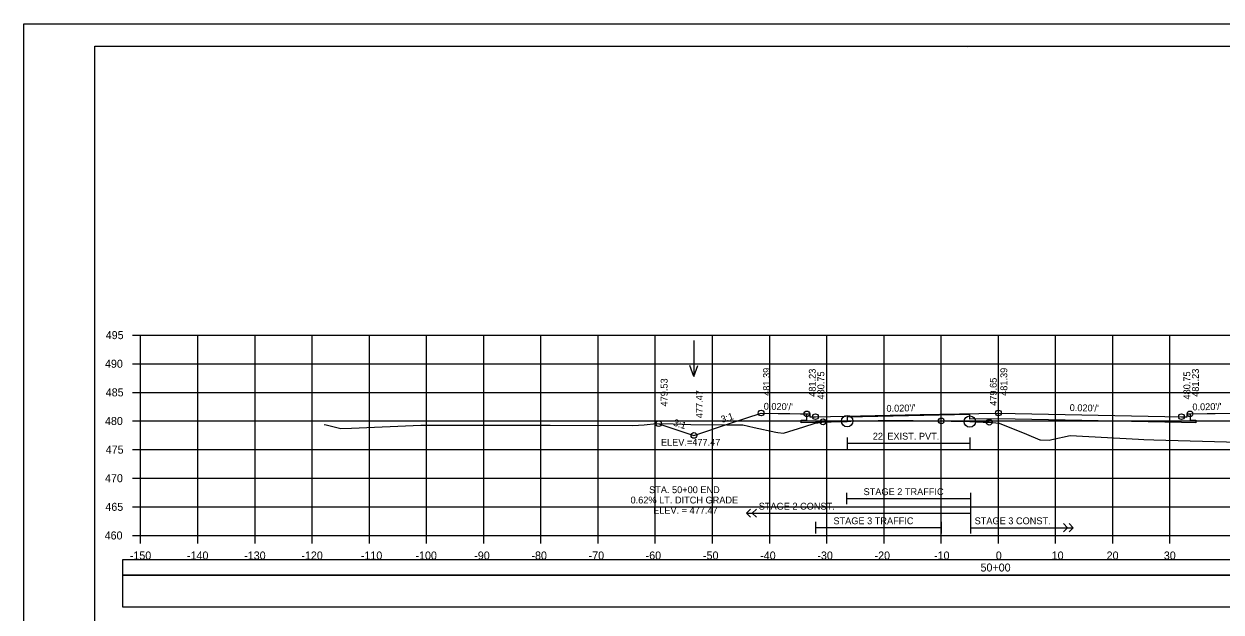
# Model space of a CAD drawing. Extents: x 1371057 to 1372761, y 380005 to 390517.
# Drawn here: x 1371390.5 to 1371599.8, y 383102.4 to 383205.1 of the extents above; entities that cross this region are included whole.
import ezdxf

# ---------------------------------------------------------------- set-up
doc = ezdxf.new("R2010")
doc.units = 0
for name, color, linetype in [('R_Alt Surface', 7, 'Continuous'), ('R_Axis', 7, 'Continuous'), ('R_Axis Annot', 7, 'Continuous'), ('R_Border', 7, 'Continuous'), ('R_Detour', 7, 'Continuous'), ('R_Dimension', 7, 'Continuous'), ('R_Exist Surface', 7, 'Continuous'), ('R_Fin Surface', 7, 'Continuous'), ('R_Grid', 7, 'Continuous'), ('R_No Plot', 7, 'Continuous'), ('R_Striping', 7, 'Continuous'), ('R_Water', 7, 'Continuous'), ('R_Water Annot', 7, 'Continuous'), ('R_Xsect Elev', 7, 'Continuous'), ('R_Xsect Slope', 7, 'Continuous')]:
    doc.layers.add(name, color=color, linetype=linetype)

msp = doc.modelspace()

# ---------------------------------------------------------------- linework, layer by layer
at = {"layer": 'R_Alt Surface'}
for points in [[(1371594.37, 383137.02), (1371594.37, 383135.94), (1371595.37, 383135.92), (1371595.37, 383135.49), (1371592.87, 383135.54), (1371560.87, 383136.18), (1371555.86, 383136.08), (1371555.86, 383136.91), (1371534.42, 383136.48), (1371534.42, 383135.65), (1371528.87, 383135.54), (1371526.37, 383135.49), (1371526.37, 383135.92), (1371527.37, 383135.94), (1371527.37, 383137.02)], [(1371594.37, 383137.02), (1371594.37, 383135.94), (1371595.37, 383135.92), (1371595.37, 383135.49), (1371592.87, 383135.54), (1371560.87, 383136.18), (1371555.86, 383136.08), (1371555.86, 383136.91), (1371534.42, 383136.48), (1371534.42, 383135.65), (1371528.87, 383135.54), (1371526.37, 383135.49), (1371526.37, 383135.92), (1371527.37, 383135.94), (1371527.37, 383137.02)], [(1371534.42, 383132.93), (1371534.42, 383130.93)], [(1371555.86, 383132.93), (1371555.86, 383130.93)], [(1371534.42, 383131.93), (1371555.86, 383131.93)]]:
    msp.add_lwpolyline(points, dxfattribs=at)
at = {"layer": 'R_Axis'}
for p, q in [((1371409.47, 383150.79), (1371410.87, 383150.79)), ((1371410.87, 383115.79), (1371410.87, 383150.79)), ((1371409.47, 383145.79), (1371410.87, 383145.79)), ((1371409.47, 383140.79), (1371410.87, 383140.79)), ((1371409.47, 383135.79), (1371410.87, 383135.79)), ((1371409.47, 383130.79), (1371410.87, 383130.79)), ((1371409.47, 383125.79), (1371410.87, 383125.79)), ((1371409.47, 383120.79), (1371410.87, 383120.79)), ((1371409.47, 383115.79), (1371410.87, 383115.79)), ((1371410.87, 383115.79), (1371710.87, 383115.79)), ((1371410.87, 383114.39), (1371410.87, 383115.79)), ((1371420.87, 383114.39), (1371420.87, 383115.79)), ((1371430.87, 383114.39), (1371430.87, 383115.79)), ((1371440.87, 383114.39), (1371440.87, 383115.79)), ((1371450.87, 383114.39), (1371450.87, 383115.79)), ((1371460.87, 383114.39), (1371460.87, 383115.79)), ((1371470.87, 383114.39), (1371470.87, 383115.79)), ((1371480.87, 383114.39), (1371480.87, 383115.79)), ((1371490.87, 383114.39), (1371490.87, 383115.79)), ((1371500.87, 383114.39), (1371500.87, 383115.79)), ((1371510.87, 383114.39), (1371510.87, 383115.79)), ((1371520.87, 383114.39), (1371520.87, 383115.79)), ((1371530.87, 383114.39), (1371530.87, 383115.79)), ((1371540.87, 383114.39), (1371540.87, 383115.79)), ((1371550.87, 383114.39), (1371550.87, 383115.79)), ((1371560.87, 383114.39), (1371560.87, 383115.79)), ((1371570.87, 383114.39), (1371570.87, 383115.79)), ((1371580.87, 383114.39), (1371580.87, 383115.79)), ((1371590.87, 383114.39), (1371590.87, 383115.79))]:
    msp.add_line(p, q, dxfattribs=at)
at = {"layer": 'R_Border'}
for p, q in [((1371402.87, 383201.25), (1371719.05, 383201.25)), ((1371402.87, 382995.79), (1371402.87, 383201.25)), ((1371555.39, 383200.99), (1371555.39, 383200.99)), ((1371555.39, 383200.99), (1371555.39, 383200.99))]:
    msp.add_line(p, q, dxfattribs=at)
at = {"layer": 'R_Detour'}
msp.add_lwpolyline([(1371407.72, 383108.84), (1371714.03, 383108.84), (1371714.03, 383111.54), (1371407.72, 383111.54)], close=True, dxfattribs=at)
at = {"layer": 'R_Dimension'}
msp.add_lwpolyline([(1371407.72, 383103.32), (1371714.03, 383103.32), (1371714.03, 383108.84), (1371407.72, 383108.84)], close=True, dxfattribs=at)
at = {"layer": 'R_Exist Surface'}
msp.add_lwpolyline([(1371442.97, 383135.2), (1371443.34, 383135.1), (1371445.88, 383134.46), (1371447.73, 383134.51), (1371459.86, 383135.03), (1371462.7, 383135.05), (1371479.54, 383135.06), (1371482.46, 383135.04), (1371496.93, 383135.02), (1371498.92, 383135.12), (1371501.06, 383135.33), (1371504.02, 383135.27), (1371507.06, 383135.15), (1371513.38, 383135.11), (1371516.18, 383135.14), (1371518.13, 383134.67), (1371521.94, 383133.82), (1371522.29, 383133.77), (1371523.27, 383133.68), (1371526.82, 383134.75), (1371528.81, 383135.43), (1371529.83, 383135.5), (1371530.2, 383135.64), (1371533.88, 383135.75), (1371534.42, 383135.77), (1371534.48, 383135.77), (1371535.08, 383135.78), (1371539.81, 383135.86), (1371540.74, 383135.86), (1371544.51, 383135.89), (1371545.03, 383135.88), (1371545.11, 383135.88), (1371545.11, 383135.88), (1371545.11, 383135.88), (1371545.98, 383135.87), (1371552.63, 383135.78), (1371553.05, 383135.77), (1371555.86, 383135.68), (1371558.21, 383135.59), (1371559.27, 383135.56), (1371560.44, 383135.46), (1371560.97, 383135.43), (1371565.8, 383133.46), (1371568.13, 383132.51), (1371568.21, 383132.51), (1371569.75, 383132.45), (1371570.2, 383132.56), (1371573.42, 383133.26), (1371585.34, 383132.59), (1371586.3, 383132.53), (1371588.04, 383132.49), (1371609.25, 383131.89)], dxfattribs=at)
at = {"layer": 'R_Fin Surface'}
msp.add_lwpolyline([(1371501.46, 383135.32), (1371507.62, 383133.27), (1371513.99, 383135.39), (1371519.37, 383137.18), (1371519.37, 383137.18), (1371522.38, 383137.12), (1371524.37, 383137.08), (1371526.25, 383137.05), (1371527.37, 383137.02), (1371527.87, 383137.02), (1371527.88, 383136.52), (1371528.87, 383136.54), (1371547.18, 383136.91), (1371560.87, 383137.18), (1371592.87, 383136.54), (1371592.87, 383136.54), (1371593.87, 383136.52), (1371593.87, 383136.71), (1371593.87, 383137.02), (1371594.36, 383137.02), (1371594.37, 383137.02), (1371597.37, 383137.08), (1371598.77, 383137.11), (1371602.37, 383137.18)], dxfattribs=at)
at = {"layer": 'R_Grid'}
for p, q in [((1371410.87, 383150.79), (1371710.87, 383150.79)), ((1371410.87, 383115.79), (1371410.87, 383150.79)), ((1371420.87, 383115.79), (1371420.87, 383150.79)), ((1371430.87, 383115.79), (1371430.87, 383150.79)), ((1371440.87, 383115.79), (1371440.87, 383150.79)), ((1371450.87, 383115.79), (1371450.87, 383150.79)), ((1371460.87, 383115.79), (1371460.87, 383150.79)), ((1371470.87, 383115.79), (1371470.87, 383150.79)), ((1371480.87, 383115.79), (1371480.87, 383150.79)), ((1371490.87, 383115.79), (1371490.87, 383150.79)), ((1371500.87, 383115.79), (1371500.87, 383150.79)), ((1371510.87, 383115.79), (1371510.87, 383150.79)), ((1371520.87, 383115.79), (1371520.87, 383150.79)), ((1371530.87, 383115.79), (1371530.87, 383150.79)), ((1371540.87, 383115.79), (1371540.87, 383150.79)), ((1371550.87, 383115.79), (1371550.87, 383150.79)), ((1371560.87, 383115.79), (1371560.87, 383150.79)), ((1371570.87, 383115.79), (1371570.87, 383150.79)), ((1371580.87, 383115.79), (1371580.87, 383150.79)), ((1371590.87, 383115.79), (1371590.87, 383150.79)), ((1371410.87, 383145.79), (1371710.87, 383145.79)), ((1371410.87, 383140.79), (1371710.87, 383140.79)), ((1371410.87, 383135.79), (1371710.87, 383135.79)), ((1371410.87, 383130.79), (1371710.87, 383130.79)), ((1371410.87, 383125.79), (1371710.87, 383125.79)), ((1371410.87, 383120.79), (1371710.87, 383120.79)), ((1371410.87, 383115.79), (1371710.87, 383115.79))]:
    msp.add_line(p, q, dxfattribs=at)
at = {"layer": 'R_No Plot'}
msp.add_line((1371390.47, 383205.15), (1371723.8, 383205.15), dxfattribs=at)
for points in [[(1371390.46, 383205.15), (1371723.8, 383205.15), (1371723.8, 382991.81), (1371390.46, 382991.81)], [(1371636.79, 383201.25), (1371656.41, 383201.25), (1371656.41, 383191.37), (1371672.52, 383191.37), (1371695.72, 383191.37), (1371695.84, 383163.21), (1371719.05, 383163.21), (1371719.05, 382995.79), (1371402.87, 382995.79), (1371402.87, 383201.25)]]:
    msp.add_lwpolyline(points, close=True, dxfattribs=at)
for centre, radius in [((1371519.37, 383137.18), 0.5), ((1371527.37, 383137.02), 0.5), ((1371528.87, 383136.54), 0.5), ((1371560.87, 383137.18), 0.5), ((1371592.87, 383136.54), 0.5), ((1371594.37, 383137.02), 0.5), ((1371501.46, 383135.32), 0.5), ((1371530.2, 383135.64), 0.5), ((1371534.42, 383135.77), 1), ((1371550.87, 383135.81), 0.5), ((1371555.86, 383135.68), 1), ((1371559.27, 383135.56), 0.5), ((1371507.62, 383133.27), 0.5)]:
    msp.add_circle(centre, radius, dxfattribs=at)
at = {"layer": 'R_Striping'}
for p, q in [((1371534.32, 383123.24), (1371534.32, 383121.24)), ((1371555.96, 383123.24), (1371555.96, 383116.15)), ((1371516.83, 383119.7), (1371517.54, 383120.4)), ((1371517.83, 383119.7), (1371518.54, 383120.4)), ((1371534.32, 383122.24), (1371555.96, 383122.24)), ((1371516.83, 383119.7), (1371555.96, 383119.7)), ((1371517.54, 383118.99), (1371516.83, 383119.7)), ((1371518.54, 383118.99), (1371517.83, 383119.7)), ((1371528.87, 383118.15), (1371528.87, 383116.15)), ((1371550.87, 383118.15), (1371550.87, 383116.15)), ((1371550.87, 383117.15), (1371528.87, 383117.15)), ((1371555.96, 383117.15), (1371573.96, 383117.15)), ((1371555.99, 383117.15), (1371565.99, 383117.15)), ((1371572.96, 383117.15), (1371572.25, 383117.86)), ((1371572.25, 383116.45), (1371572.96, 383117.15)), ((1371573.96, 383117.15), (1371573.25, 383117.86)), ((1371573.25, 383116.45), (1371573.96, 383117.15))]:
    msp.add_line(p, q, dxfattribs=at)
at = {"layer": 'R_Water Annot'}
for p, q in [((1371507.62, 383149.86), (1371507.62, 383143.58)), ((1371507.62, 383143.58), (1371506.92, 383145.5)), ((1371507.62, 383143.58), (1371508.32, 383145.5))]:
    msp.add_line(p, q, dxfattribs=at)
at = {"layer": 'R_Xsect Elev'}
msp.add_line((1371560.87, 383135.44), (1371560.87, 383145.44), dxfattribs=at)

# ---------------------------------------------------------------- texts
at = {"layer": 'R_Axis Annot'}
for s, p in [('495', (1371404.77, 383150.09)), ('490', (1371404.64, 383145.09)), ('485', (1371404.77, 383140.09)), ('480', (1371404.64, 383135.09)), ('475', (1371404.77, 383130.09)), ('470', (1371404.64, 383125.09)), ('465', (1371404.7, 383120.09)), ('460', (1371404.58, 383115.09)), ('-150', (1371408.98, 383111.59)), ('-140', (1371418.98, 383111.59)), ('-130', (1371428.98, 383111.59)), ('-120', (1371438.98, 383111.59)), ('-110', (1371449.38, 383111.59)), ('-100', (1371458.93, 383111.59)), ('-90', (1371469.21, 383111.59)), ('-80', (1371479.21, 383111.59)), ('-70', (1371489.21, 383111.59)), ('-60', (1371499.18, 383111.59)), ('-50', (1371509.21, 383111.59)), ('-40', (1371519.21, 383111.59)), ('-30', (1371529.21, 383111.59)), ('-20', (1371539.21, 383111.59)), ('-10', (1371549.61, 383111.59)), ('0', (1371560.41, 383111.59)), ('10', (1371570.18, 383111.59)), ('20', (1371579.79, 383111.59)), ('30', (1371589.79, 383111.59)), ('50+00', (1371557.74, 383109.49))]:
    msp.add_text(s, height=1.4, dxfattribs=at).set_placement(p)
at = {"layer": 'R_Striping'}
for s, p in [('STAGE 2 TRAFFIC', (1371537.29, 383122.84)), ('STAGE 2 CONST.', (1371518.96, 383120.3)), ('STAGE 3 TRAFFIC', (1371532.02, 383117.75)), ('STAGE 3 CONST.', (1371556.71, 383117.75))]:
    msp.add_text(s, height=1.2, dxfattribs=at).set_placement(p)
at = {"layer": 'R_Water'}
msp.add_text("22' EXIST. PVT.", height=1.2, dxfattribs=at).set_placement((1371538.9, 383132.53))
at = {"layer": 'R_Xsect Elev'}
for s, p in [('481.39', (1371520.92, 383140.18)), ('481.23', (1371528.92, 383140.02)), ('480.75', (1371530.42, 383139.54)), ('479.65', (1371560.57, 383138.44)), ('481.39', (1371562.42, 383140.18)), ('480.75', (1371594.42, 383139.54)), ('481.23', (1371595.92, 383140.02)), ('479.53', (1371503.01, 383138.32)), ('477.47', (1371509.17, 383136.27))]:
    msp.add_text(s, height=1.2, rotation=90, dxfattribs=at).set_placement(p)
for s, p in [('ELEV.=477.47', (1371501.85, 383131.47)), ('0.62% LT. DITCH GRADE', (1371496.54, 383121.38)), ('STA. 50+00 END ', (1371499.78, 383123.18)), ('ELEV. = 477.47', (1371500.49, 383119.58))]:
    msp.add_text(s, height=1.2, dxfattribs=at).set_placement(p)
at = {"layer": 'R_Xsect Slope'}
for s, rotation, p in [('3:1', 18.4349, (1371512.55, 383135.44)), ("0.020'/'", 358.8542, (1371519.82, 383137.77)), ("0.020'/'", 1.1458, (1371541.3, 383137.39)), ("0.020'/'", 358.8542, (1371573.32, 383137.53)), ("0.020'/'", 1.1457, (1371594.8, 383137.63)), ('3:1', 341.5617, (1371503.91, 383135.03))]:
    msp.add_text(s, height=1.2, rotation=rotation, dxfattribs=at).set_placement(p)

doc.saveas('drawing.dxf')
